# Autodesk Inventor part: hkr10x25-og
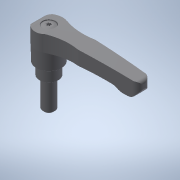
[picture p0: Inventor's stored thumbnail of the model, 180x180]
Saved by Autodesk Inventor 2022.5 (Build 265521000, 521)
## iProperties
Created: 2017-09
Part Number: hkr10x25-og
Material: 一般
Document SubType Name: Modeling
Designer: imaocorp
Density: 1 g/cm^3
Appearance: 既定
Author: imaocorp
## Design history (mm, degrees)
node "hkr10x25-og.x_t1"
node "hkr10x25-og"
node "Base1"
